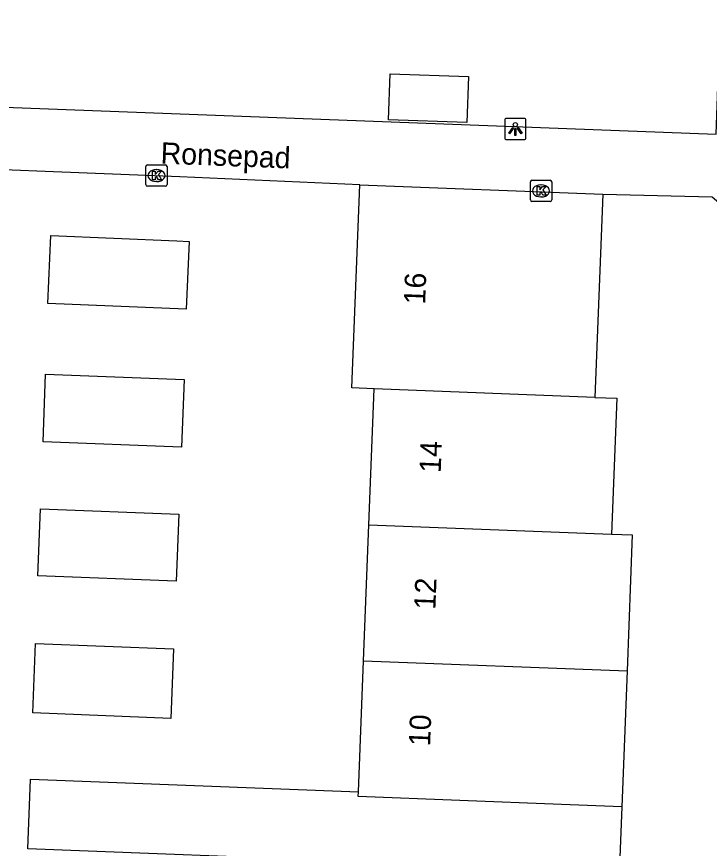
# Model space of a CAD drawing. Extents: x 160732 to 162105, y 387428 to 388479.
# Drawn here: x 161124.89 to 161157.41, y 387650.15 to 387689.18 of the extents above; entities that cross this region are included whole.
import ezdxf

# ---------------------------------------------------------------- set-up
doc = ezdxf.new("R2010")
doc.units = 0
for name, color, linetype in [('IMGEO_Kolk', 7, 'Continuous'), ('IMGEO_Lichtpunt', 7, 'Continuous'), ('IMGEO_Openbare_ruimte_label', 7, 'Continuous'), ('IMGEO_Pand', 7, 'Continuous'), ('IMGEO_Pand_nummerreeks', 7, 'Continuous'), ('IMGEO_Pand_vergunning_verleend', 7, 'Continuous'), ('IMGEO_Voetpad_open', 7, 'Continuous')]:
    doc.layers.add(name, color=color, linetype=linetype)

msp = doc.modelspace()

# ---------------------------------------------------------------- linework, layer by layer
at = {"layer": 'IMGEO_Kolk'}
for p, q in [((161131.024, 387682.219), (161131.876, 387682.219)), ((161130.949, 387681.293), (161130.949, 387682.145)), ((161131.437, 387681.999), (161131.462, 387681.999)), ((161131.95, 387682.145), (161131.95, 387681.293)), ((161131.46, 387681.439), (161131.435, 387681.439)), ((161149.003, 387680.574), (161149.003, 387681.426)), ((161149.078, 387681.5), (161149.93, 387681.5)), ((161150.004, 387681.426), (161150.004, 387680.574)), ((161131.876, 387681.219), (161131.024, 387681.219)), ((161149.491, 387681.28), (161149.516, 387681.28)), ((161149.514, 387680.72), (161149.489, 387680.72)), ((161149.93, 387680.5), (161149.078, 387680.5))]:
    msp.add_line(p, q, dxfattribs=at)
for points in [[(161131.024, 387682.219), (161131.876, 387682.219)], [(161130.949, 387681.293), (161130.949, 387682.145)], [(161131.27, 387681.919), (161131.393, 387681.919), (161131.393, 387681.768), (161131.523, 387681.919), (161131.687, 387681.919), (161131.541, 387681.768), (161131.694, 387681.519), (161131.542, 387681.519), (161131.457, 387681.683), (161131.393, 387681.616), (161131.393, 387681.519), (161131.27, 387681.519), (161131.27, 387681.919)], [(161131.95, 387682.145), (161131.95, 387681.293)], [(161149.003, 387680.574), (161149.003, 387681.426)], [(161149.078, 387681.5), (161149.93, 387681.5)], [(161150.004, 387681.426), (161150.004, 387680.574)], [(161131.876, 387681.219), (161131.024, 387681.219)], [(161149.324, 387681.2), (161149.447, 387681.2), (161149.447, 387681.049), (161149.577, 387681.2), (161149.741, 387681.2), (161149.595, 387681.049), (161149.748, 387680.8), (161149.596, 387680.8), (161149.511, 387680.964), (161149.447, 387680.897), (161149.447, 387680.8), (161149.324, 387680.8), (161149.324, 387681.2)], [(161149.93, 387680.5), (161149.078, 387680.5)]]:
    msp.add_lwpolyline(points, dxfattribs=at)
for centre, start, end in [((161131.026, 387682.143), 91.552, 178.448), ((161131.026, 387682.143), 91.552, 178.448), ((161131.874, 387682.143), 1.552, 88.448), ((161131.874, 387682.143), 1.552, 88.448), ((161149.08, 387681.424), 91.552, 178.448), ((161149.08, 387681.424), 91.552, 178.448), ((161149.928, 387681.424), 1.552, 88.448), ((161149.928, 387681.424), 1.552, 88.448), ((161131.026, 387681.295), 181.552, 268.448), ((161131.026, 387681.295), 181.552, 268.448), ((161131.874, 387681.295), 271.552, 358.448), ((161131.874, 387681.295), 271.552, 358.448), ((161149.08, 387680.576), 181.552, 268.448), ((161149.08, 387680.576), 181.552, 268.448), ((161149.928, 387680.576), 271.552, 358.448), ((161149.928, 387680.576), 271.552, 358.448)]:
    msp.add_arc(centre, 0.0765, start, end, dxfattribs=at)
for centre, major_axis, ratio, start_param, end_param in [((161131.436, 387681.719), (-0.387, 0.002), 0.722429, 4.712389, 7.853982), ((161131.461, 387681.719), (-0.39, 0.002), 0.717154, 1.570796, 4.712389), ((161149.49, 387681), (-0.387, 0.002), 0.722429, 4.712389, 7.853982), ((161149.515, 387681), (-0.39, 0.002), 0.717154, 1.570796, 4.712389)]:
    msp.add_ellipse(centre, major_axis=major_axis, ratio=ratio, start_param=start_param, end_param=end_param, dxfattribs=at)
at = {"layer": 'IMGEO_Lichtpunt'}
for p, q in [((161147.8, 387684.309), (161147.8, 387683.502)), ((161147.8, 387684.309), (161147.8, 387683.502)), ((161148.702, 387684.404), (161147.894, 387684.404)), ((161148.702, 387684.404), (161147.894, 387684.404)), ((161148.796, 387683.502), (161148.796, 387684.309)), ((161148.796, 387683.502), (161148.796, 387684.309)), ((161147.894, 387683.408), (161148.702, 387683.408)), ((161147.894, 387683.408), (161148.702, 387683.408))]:
    msp.add_line(p, q, dxfattribs=at)
for points in [[(161148.174, 387683.973), (161148.213, 387683.945), (161148.025, 387683.683), (161147.987, 387683.71), (161148.174, 387683.973)], [(161148.276, 387683.925), (161148.323, 387683.925), (161148.323, 387683.603), (161148.276, 387683.603), (161148.276, 387683.925)], [(161148.386, 387683.945), (161148.424, 387683.972), (161148.611, 387683.71), (161148.572, 387683.682), (161148.386, 387683.945)]]:
    msp.add_lwpolyline(points, dxfattribs=at)
msp.add_circle((161148.299, 387684.107), 0.0994, dxfattribs=at)
for centre, start, end in [((161147.894, 387684.309), 90, 180), ((161147.894, 387684.309), 90, 180), ((161148.702, 387684.309), 0, 90), ((161148.702, 387684.309), 0, 90), ((161147.894, 387683.502), 180, 270), ((161147.894, 387683.502), 180, 270), ((161148.702, 387683.502), 270, 0), ((161148.702, 387683.502), 270, 360)]:
    msp.add_arc(centre, 0.0946, start, end, dxfattribs=at)
at = {"layer": 'IMGEO_Pand'}
for points in [[(161141.664, 387671.712), (161140.626, 387671.752), (161140.997, 387681.285)], [(161140.997, 387681.285), (161152.408, 387680.842)], [(161152.408, 387680.842), (161152.037, 387671.309)], [(161126.349, 387675.723), (161126.486, 387678.907), (161132.413, 387678.653), (161132.982, 387678.629), (161132.845, 387675.445), (161126.349, 387675.723)], [(161126.124, 387669.228), (161126.247, 387672.401), (161132.743, 387672.149), (161132.619, 387668.976), (161126.124, 387669.228)], [(161141.416, 387665.334), (161141.664, 387671.712)], [(161152.037, 387671.309), (161141.664, 387671.712)], [(161152.037, 387671.309), (161153.057, 387671.269), (161152.809, 387664.891)], [(161125.888, 387662.937), (161126.01, 387666.086), (161132.499, 387665.834), (161132.376, 387662.685), (161125.888, 387662.937)], [(161141.168, 387658.955), (161141.416, 387665.334)], [(161141.416, 387665.334), (161152.809, 387664.891)], [(161152.809, 387664.891), (161153.788, 387664.853), (161153.54, 387658.474)], [(161132.13, 387656.249), (161125.642, 387656.501), (161125.769, 387659.758), (161132.256, 387659.506), (161132.13, 387656.249)], [(161140.929, 387652.799), (161141.168, 387658.955)], [(161141.168, 387658.955), (161153.54, 387658.474)], [(161153.54, 387658.474), (161153.292, 387652.096)], [(161140.672, 387646.199), (161140.801, 387649.524), (161125.41, 387650.122), (161125.538, 387653.397), (161140.929, 387652.799)], [(161153.292, 387652.096), (161150.464, 387652.206), (161140.92, 387652.577), (161140.929, 387652.799)], [(161153.292, 387652.096), (161153.046, 387645.765), (161150.218, 387645.875), (161150.216, 387645.828)]]:
    msp.add_lwpolyline(points, dxfattribs=at)
at = {"layer": 'IMGEO_Pand_vergunning_verleend'}
msp.add_lwpolyline([(161142.416, 387686.498), (161146.095, 387686.371), (161146.02, 387684.215), (161142.338, 387684.342), (161142.416, 387686.498)], dxfattribs=at)
at = {"layer": 'IMGEO_Voetpad_open'}
for points in [[(161115.604, 387711.866), (161115.535, 387710.66), (161115.689, 387710.643), (161115.059, 387694.991), (161114.651, 387685.302), (161122.654, 387684.997), (161157.729, 387683.661), (161158.641, 387709.529), (161158.67, 387710.144)], [(161140.997, 387681.285), (161132.542, 387681.663), (161126.614, 387681.9), (161124.277, 387681.994)], [(161152.408, 387680.842), (161157.536, 387680.714), (161158.458, 387679.941), (161159.084, 387678.892), (161158.688, 387671.93)]]:
    msp.add_lwpolyline(points, dxfattribs=at)

# ---------------------------------------------------------------- texts
at = {"layer": 'IMGEO_Openbare_ruimte_label'}
msp.add_text('Ronsepad', height=1, rotation=357.8216, dxfattribs=at).set_placement((161131.633, 387682.284))
at = {"layer": 'IMGEO_Pand_nummerreeks'}
for s, rotation, p in [('16', 87.7739, (161144.061, 387675.66)), ('14', 87.773, (161144.793, 387667.757)), ('12', 87.773, (161144.543, 387661.339)), ('10', 87.773, (161144.294, 387654.929))]:
    msp.add_text(s, height=1, rotation=rotation, dxfattribs=at).set_placement(p)

doc.saveas('drawing.dxf')
